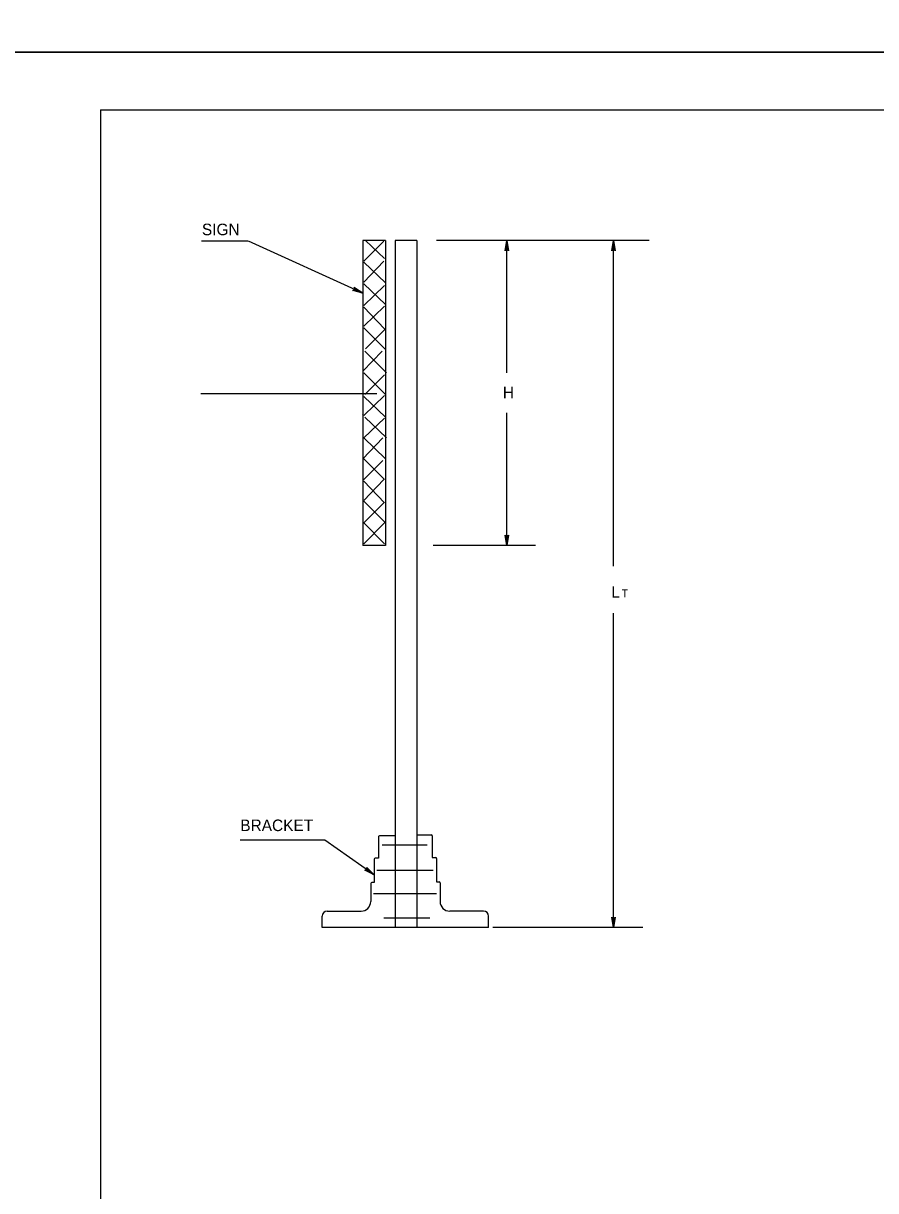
# Model space of a CAD drawing. Extents: x 637580 to 641008, y 294594 to 295782.
# Drawn here: x 639282.3 to 639503.7, y 294891.9 to 295195.1 of the extents above; entities that cross this region are included whole.
import ezdxf

# ---------------------------------------------------------------- set-up
doc = ezdxf.new("R2010")
doc.units = 0
for name, color, linetype in [('1', 7, 'Continuous'), ('2', 7, 'Continuous'), ('3', 7, 'Continuous'), ('PLT-BNDY', 7, 'Continuous')]:
    doc.layers.add(name, color=color, linetype=linetype)

# ---------------------------------------------------------------- blocks, each defined once
blk = doc.blocks.new('RARROW')
at = {"layer": '3'}
blk.add_lwpolyline([(-2.2695, 0.285), (-2.184875, 0.12075), (0, 0), (-2.2695, 0.285), (-2.38575, 0.384625), (0, 0), (-2.183125, -0.108), (-2.262875, -0.2705), (0, 0), (-2.38575, -0.379125), (-2.262875, -0.2705)], dxfattribs=at)

msp = doc.modelspace()

# ---------------------------------------------------------------- linework, layer by layer
at = {"layer": '1'}
for q in [(640088.31, 295172.63), (639302.31, 294608.63)]:
    msp.add_line((639302.31, 295172.63), q, dxfattribs=at)
at = {"layer": '2'}
for p, q in [((639340.58, 295138.53), (639328.59, 295138.53)), ((639370.52, 295125.02), (639340.8, 295138.53)), ((639370.52, 295138.75), (639370.52, 295059.51)), ((639376.37, 295138.75), (639370.52, 295138.75)), ((639375.92, 295138.53), (639370.74, 295133.35)), ((639371.19, 295138.75), (639376.15, 295134.02)), ((639376.37, 295138.75), (639376.37, 295059.51)), ((639378.85, 295138.75), (639378.85, 294960.23)), ((639384.48, 295138.75), (639378.85, 295138.75)), ((639384.48, 295138.75), (639384.48, 294960.23)), ((639444.81, 295138.75), (639389.65, 295138.75)), ((639407.89, 295104.31), (639407.89, 295138.75)), ((639435.58, 295054.11), (639435.58, 295138.75)), ((639375.92, 295133.35), (639370.74, 295127.94)), ((639370.74, 295133.12), (639376.37, 295127.72)), ((639370.74, 295127.49), (639376.37, 295122.09)), ((639376.15, 295127.04), (639370.74, 295121.87)), ((639376.15, 295121.64), (639370.74, 295116.46)), ((639370.74, 295121.42), (639376.15, 295115.79)), ((639370.74, 295116.01), (639376.37, 295110.39)), ((639376.37, 295115.79), (639371.19, 295110.61)), ((639375.47, 295109.94), (639370.52, 295104.76)), ((639370.97, 295109.94), (639376.6, 295104.31)), ((639370.74, 295104.31), (639376.37, 295098.68)), ((639376.15, 295103.86), (639370.97, 295098.68)), ((639374.12, 295098.9), (639328.42, 295098.9)), ((639376.15, 295098.45), (639370.74, 295093.28)), ((639370.74, 295098.23), (639376.37, 295092.83)), ((639370.29, 295093.5), (639370.29, 295093.5)), ((639407.89, 295059.51), (639407.89, 295093.95)), ((639376.15, 295092.6), (639370.74, 295087.42)), ((639370.97, 295092.83), (639376.6, 295087.42)), ((639375.7, 295087.42), (639370.52, 295082.02)), ((639370.74, 295087.42), (639376.37, 295082.02)), ((639375.7, 295081.57), (639370.52, 295076.39)), ((639370.74, 295082.02), (639376.15, 295076.62)), ((639375.92, 295076.62), (639370.74, 295071.22)), ((639370.74, 295076.17), (639376.15, 295070.54)), ((639370.74, 295070.99), (639376.37, 295065.36)), ((639375.92, 295070.54), (639370.74, 295065.36)), ((639376.15, 295065.36), (639370.74, 295059.96)), ((639370.74, 295065.36), (639376.15, 295059.96)), ((639376.37, 295059.51), (639370.52, 295059.51)), ((639415.32, 295059.51), (639388.75, 295059.51)), ((639435.58, 294960.23), (639435.58, 295041.95)), ((639384.48, 294984.32), (639388.28, 294984.32)), ((639360.61, 294982.97), (639338.62, 294982.97)), ((639373.45, 294973.96), (639360.61, 294982.97)), ((639374.57, 294983.87), (639374.57, 294978.24)), ((639378.85, 294984.1), (639374.8, 294984.1)), ((639387.18, 294981.62), (639375.47, 294981.62)), ((639388.53, 294984.07), (639388.53, 294978.47)), ((639374.57, 294978.24), (639373.7, 294978.24)), ((639388.53, 294978.47), (639389.4, 294978.47)), ((639389.65, 294978.22), (639389.65, 294972.16)), ((639373.45, 294977.99), (639373.45, 294971.94)), ((639388.75, 294975.09), (639374.12, 294975.09)), ((639389.65, 294972.16), (639390.3, 294972.16)), ((639372.54, 294971.69), (639372.54, 294967.01)), ((639373.45, 294971.94), (639372.79, 294971.94)), ((639390.55, 294971.91), (639390.55, 294967.01)), ((639389.65, 294969.01), (639373.22, 294969.01)), ((639359.94, 294960.23), (639359.94, 294963.21)), ((639361.24, 294964.51), (639370.04, 294964.51)), ((639401.86, 294964.51), (639393.05, 294964.51)), ((639403.16, 294960.23), (639403.16, 294963.21)), ((639403.16, 294960.23), (639359.94, 294960.23)), ((639387.85, 294962.71), (639375.92, 294962.71)), ((639403.16, 294960.23), (639403.16, 294960.23)), ((639443.23, 294960.23), (639404.29, 294960.23))]:
    msp.add_line(p, q, dxfattribs=at)
msp.add_ellipse((639374.79, 294983.88), major_axis=(0, -0.214), ratio=0.996388, start_param=3.141593, end_param=4.712389, dxfattribs=at)
at = {"layer": '3'}
for centre, radius, start, end in [((639388.28, 294984.07), 0.25, 0, 90), ((639373.7, 294977.99), 0.25, 90, 180), ((639389.4, 294978.22), 0.25, 0, 90), ((639390.3, 294971.91), 0.25, 0, 90), ((639372.79, 294971.69), 0.25, 90, 180), ((639370.04, 294967.01), 2.5, 270, 0), ((639393.05, 294967.01), 2.5, 180, 270), ((639361.24, 294963.21), 1.3, 90, 180), ((639401.86, 294963.21), 1.3, 0, 90)]:
    msp.add_arc(centre, radius, start, end, dxfattribs=at)
at = {"layer": 'PLT-BNDY'}
for points in [[(639262.31, 295781.63), (640103.31, 295781.63), (640103.31, 295187.63), (639262.31, 295187.63)], [(639262.31, 295187.63), (640103.31, 295187.63), (640103.31, 294593.63), (639262.31, 294593.63)]]:
    msp.add_lwpolyline(points, close=True, dxfattribs=at)

# ---------------------------------------------------------------- block references
at = {"layer": '2'}
for p, xscale, yscale, rotation in [((639407.89, 295138.75), 1.1316912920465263, 1.1783664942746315, 89.99999999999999), ((639435.58, 295138.75), 1.1316912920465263, 1.1783664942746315, 89.99999999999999), ((639370.52, 295125.02), 1.1316912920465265, 1.1783664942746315, -24.745127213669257), ((639407.89, 295059.51), 1.1316912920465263, 1.1783664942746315, -90.00000000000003), ((639373.45, 294973.96), 1.1316912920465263, 1.1783664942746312, -34.83097727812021), ((639435.58, 294960.23), 1.1316912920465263, 1.1783664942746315, -90.00000000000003)]:
    msp.add_blockref('RARROW', p, dxfattribs=dict(at, xscale=xscale, yscale=yscale, rotation=rotation))

# ---------------------------------------------------------------- texts
at = {"layer": '1'}
msp.add_text('T', height=2, dxfattribs=at).set_placement((639437.73, 295046.07))
at = {"layer": '3'}
for s, p in [('SIGN', (639328.69, 295140.09)), ('H', (639406.86, 295097.71)), ('L', (639435, 295045.93)), ('BRACKET', (639338.65, 294985.31))]:
    msp.add_text(s, height=3, dxfattribs=at).set_placement(p)

doc.saveas('drawing.dxf')
